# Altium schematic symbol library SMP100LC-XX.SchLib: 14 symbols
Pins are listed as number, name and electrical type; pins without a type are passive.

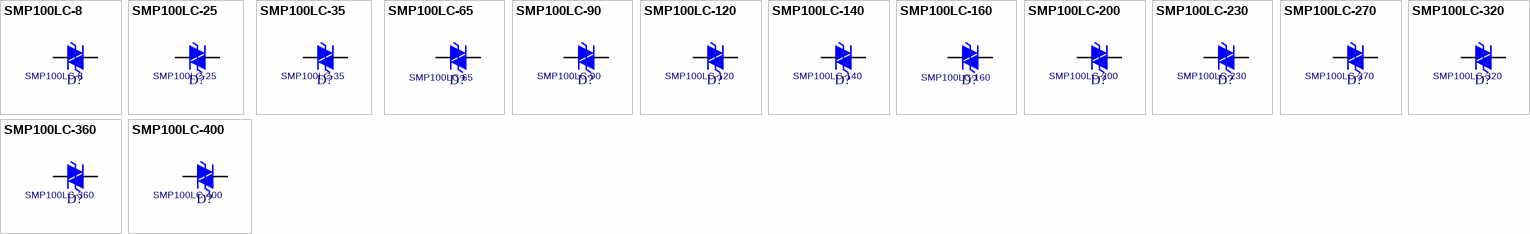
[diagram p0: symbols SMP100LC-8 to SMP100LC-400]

## SMP100LC-8
designator D?
footprint ST_SMBB
pins: 1, 2

## SMP100LC-25
designator D?
footprint ST_SMBB
pins: 1, 2

## SMP100LC-35
designator D?
footprint ST_SMBB
pins: 1, 2

## SMP100LC-65
designator D?
footprint ST_SMBB
pins: 1, 2

## SMP100LC-90
designator D?
footprint ST_SMBB
pins: 1, 2

## SMP100LC-120
designator D?
footprint ST_SMBB
pins: 1, 2

## SMP100LC-140
designator D?
footprint ST_SMBB
pins: 1, 2

## SMP100LC-160
designator D?
footprint ST_SMBB
pins: 1, 2

## SMP100LC-200
designator D?
footprint ST_SMBB
pins: 1, 2

## SMP100LC-230
designator D?
footprint ST_SMBB
pins: 1, 2

## SMP100LC-270
designator D?
footprint ST_SMBB
pins: 1, 2

## SMP100LC-320
designator D?
footprint ST_SMBB
pins: 1, 2

## SMP100LC-360
designator D?
footprint ST_SMBB
pins: 1, 2

## SMP100LC-400
designator D?
footprint ST_SMBB
pins: 1, 2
